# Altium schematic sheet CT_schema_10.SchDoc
size 147 x 119 mm
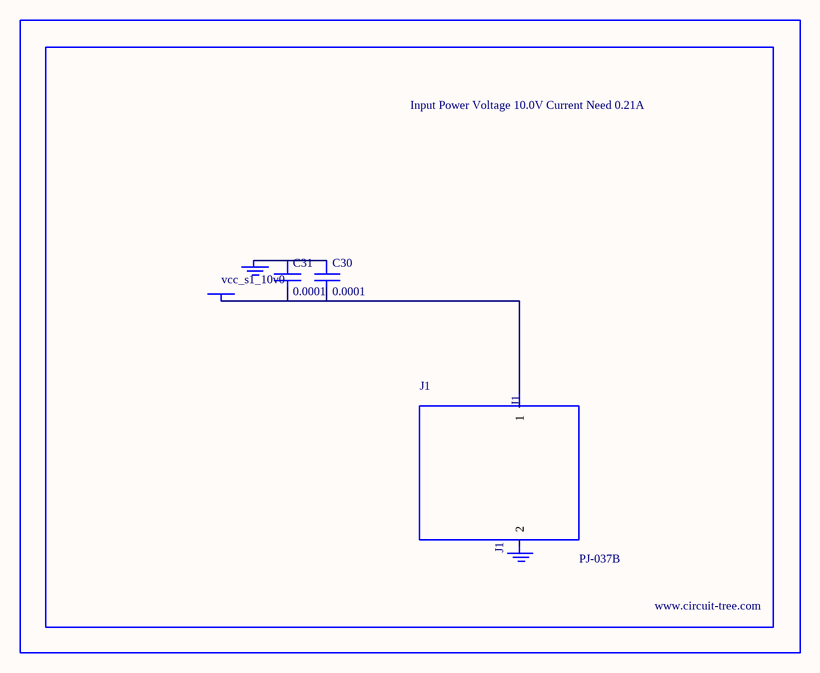
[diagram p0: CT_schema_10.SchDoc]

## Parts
BORDER9  (no value)
C30  0.0001  [EXV-9H]
C31  0.0001  [EXV-9H]
GND_INSTANCE_9_0  (no value)
GND_INSTANCE_9_1  (no value)
J1  PJ-037B  [PJ-037B_PACKAGE]
POWER_INSTANCE_9_0  vcc_s1_10v0

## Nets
NetC30_1: C30.1 C31.1 GND_INSTANCE_9_0.0(GND)
NetC30_2: C30.2 C31.2 J1.1 POWER_INSTANCE_9_0.0(PWR)

Not connected (* = marked no-connect by the designer): GND_INSTANCE_9_1 0(GND); J1 2

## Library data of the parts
BORDER9 = BORDER_PAGE9
C30 C31 = EDK107M035A9HAA
GND_INSTANCE_9_0 GND_INSTANCE_9_1 = GND
POWER_INSTANCE_9_0 = PWR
